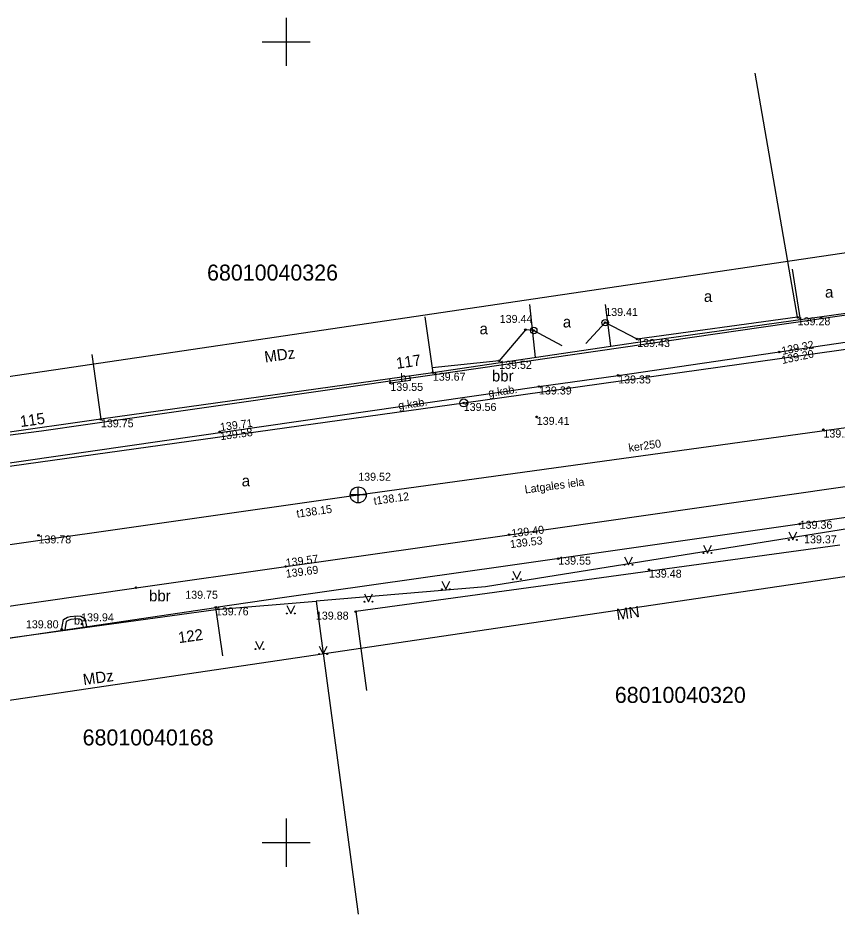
# Model space of a CAD drawing. Extents: x 728785 to 728985, y 273137 to 273208.
# Drawn here: x 728883.2 to 728934.4, y 273145.5 to 273201.5 of the extents above; entities that cross this region are included whole.
import ezdxf

# ---------------------------------------------------------------- set-up
doc = ezdxf.new("R2010")
doc.units = 0
for name, color, linetype in [('APGR_SARK_####_####_#', 7, 'Continuous'), ('BUVE_BDET_####_####_#', 7, 'Continuous'), ('BUVE_BDET_####_TKST_#', 7, 'Continuous'), ('BUVE_EKAS_####_####_#', 7, 'Continuous'), ('BUVE_EKAS_ADRS_TKST_#', 7, 'Continuous'), ('BUVE_EKAS_RAKS_TKST_#', 7, 'Continuous'), ('CELI_CAPM_####_####_#', 7, 'Continuous'), ('CELI_CMAL_####_####_#', 7, 'Continuous'), ('CELI_CSEG_####_TKST_#', 7, 'Continuous'), ('CELI_IELA_####_TKST_#', 7, 'Continuous'), ('ELEK_ELEM_####_####_#', 7, 'Continuous'), ('ELEK_VADV_ZSPR_####_#', 7, 'Continuous'), ('ELEK_VADV_ZSPR_TKST_#', 7, 'Continuous'), ('GEOD_ELEM_####_####_#', 7, 'Continuous'), ('NORB_ELEM_####_####_#', 7, 'Continuous'), ('NORB_ZOGS_ZSTP_####_#', 7, 'Continuous'), ('RELJ_AATZ_####_TKST_#', 7, 'Continuous'), ('RELJ_ELEM_####_####_#', 7, 'Continuous'), ('ROBZ_KADS_####_TKST_#', 7, 'Continuous'), ('ROBZ_UZMR_####_####_#', 7, 'Continuous'), ('SKAN_ELEM_####_####_#', 7, 'Continuous'), ('SKAN_ELEM_PAST_TKST_#', 7, 'Continuous'), ('SKAN_VADP_PAST_####_#', 7, 'Continuous'), ('SKAN_VADP_PAST_TKST_#', 7, 'Continuous'), ('TERT_ELEM_####_####_#', 7, 'Continuous')]:
    doc.layers.add(name, color=color, linetype=linetype)

msp = doc.modelspace()

# ---------------------------------------------------------------- linework, layer by layer
at = {"layer": 'APGR_SARK_####_####_#'}
for points in [[(728955.084, 273187.77), (728943.86, 273188.14), (728816.642, 273169.324)], [(728957.827, 273167.668), (728945.002, 273168.092), (728819.408, 273149.515)]]:
    msp.add_lwpolyline(points, dxfattribs=at)
at = {"layer": 'BUVE_BDET_####_####_#'}
for p, q in [((728907.767, 273178.889), (728907.73, 273179.145)), ((728906.509, 273178.709), (728906.468, 273178.968)), ((728906.509, 273178.709), (728907.767, 273178.889))]:
    msp.add_line(p, q, dxfattribs=at)
for points in [[(728885.974, 273163.262), (728886.081, 273163.935), (728886.346, 273164.087), (728886.515, 273164.125), (728886.941, 273164.169), (728887.184, 273164.149), (728887.422, 273163.993), (728887.535, 273163.494)], [(728887.335, 273163.464), (728887.243, 273163.868), (728887.115, 273163.952), (728886.943, 273163.966), (728886.548, 273163.925), (728886.42, 273163.896), (728886.265, 273163.808), (728886.184, 273163.294)]]:
    msp.add_lwpolyline(points, dxfattribs=at)
at = {"layer": 'BUVE_EKAS_####_####_#'}
for p, q in [((728908.671, 273182.834), (728909.161, 273179.346)), ((728887.858, 273180.487), (728888.427, 273176.436)), ((728909.161, 273179.346), (728888.427, 273176.436)), ((728888.427, 273176.436), (728876.392, 273174.747)), ((728934.577, 273168.568), (728904.348, 273164.427)), ((728880.21, 273162.407), (728895.607, 273164.692)), ((728896.046, 273161.663), (728895.607, 273164.692)), ((728904.348, 273164.427), (728905.012, 273159.511))]:
    msp.add_line(p, q, dxfattribs=at)
at = {"layer": 'CELI_CAPM_####_####_#'}
for points in [[(728857.186, 273170.288), (728877.231, 273172.928), (728915.793, 273178.486), (728920.739, 273179.175), (728935.924, 273181.389)], [(728855.438, 273160.854), (728872.218, 273163.259), (728890.623, 273165.918), (728899.975, 273167.245), (728913.935, 273169.231), (728937.385, 273172.585), (728952.292, 273174.776)]]:
    msp.add_lwpolyline(points, dxfattribs=at)
at = {"layer": 'CELI_CMAL_####_####_#'}
for points in [[(728932.125, 273182.65), (728931.621, 273185.804)], [(728915.567, 273180.287), (728915.213, 273183.6)], [(728920.275, 273181.023), (728919.945, 273183.6)], [(728935.865, 273183.174), (728921.973, 273181.228), (728909.161, 273179.346)], [(728952.265, 273173.086), (728937.162, 273170.62), (728913.708, 273167.266), (728899.747, 273165.28), (728895.607, 273164.692)]]:
    msp.add_lwpolyline(points, dxfattribs=at)
at = {"layer": 'ELEK_ELEM_####_####_#'}
msp.add_circle((728911.092, 273177.457), 0.25, dxfattribs=at)
at = {"layer": 'ELEK_VADV_ZSPR_####_#'}
for p, q in [((728911.092, 273177.457), (728948.158, 273182.674)), ((728864.528, 273170.982), (728911.092, 273177.457))]:
    msp.add_line(p, q, dxfattribs=at)
at = {"layer": 'GEOD_ELEM_####_####_#'}
for p, q in [((728900, 273201.5), (728900, 273200)), ((728898.5, 273200), (728900, 273200)), ((728900, 273200), (728900, 273198.5)), ((728900, 273200), (728901.5, 273200)), ((728900, 273151.5), (728900, 273150)), ((728898.5, 273150), (728900, 273150)), ((728900, 273150), (728900, 273148.5)), ((728900, 273150), (728901.5, 273150))]:
    msp.add_line(p, q, dxfattribs=at)
at = {"layer": 'NORB_ELEM_####_####_#'}
for p, q in [((728919.931, 273182.471), (728918.718, 273181.177)), ((728915.467, 273181.981), (728917.23, 273181.048))]:
    msp.add_line(p, q, dxfattribs=at)
for centre in [(728919.931, 273182.471), (728915.467, 273181.981)]:
    msp.add_circle(centre, 0.202, dxfattribs=at)
at = {"layer": 'NORB_ZOGS_ZSTP_####_#'}
for points in [[(728931.95, 273182.807), (728929.304, 273198.056)], [(728931.95, 273182.807), (728921.93, 273181.449), (728919.931, 273182.471)], [(728915.467, 273181.981), (728914.949, 273182.03), (728913.303, 273180.087), (728909.117, 273179.656)]]:
    msp.add_lwpolyline(points, dxfattribs=at)
at = {"layer": 'RELJ_ELEM_####_####_#'}
for centre in [(728919.931, 273182.471), (728931.95, 273182.807), (728914.949, 273182.03), (728915.467, 273181.981), (728921.93, 273181.449), (728913.303, 273180.087), (728930.806, 273180.643), (728909.161, 273179.346), (728920.739, 273179.175), (728906.509, 273178.709), (728915.793, 273178.486), (728911.092, 273177.457), (728888.427, 273176.436), (728915.655, 273176.587), (728895.854, 273175.652), (728933.561, 273175.793), (728904.501, 273171.712), (728932.075, 273169.9), (728884.528, 273169.186), (728913.935, 273169.231), (728899.975, 273167.244), (728916.997, 273167.728), (728922.66, 273167.047), (728890.623, 273165.918), (728895.607, 273164.692), (728904.348, 273164.427), (728885.976, 273163.322), (728887.249, 273163.653)]:
    msp.add_circle(centre, 0.05, dxfattribs=at)
at = {"layer": 'ROBZ_UZMR_####_####_#'}
for p, q in [((728909.118, 273179.219), (728935.806, 273183.076)), ((728887.62, 273176.127), (728909.118, 273179.219)), ((728876.334, 273174.678), (728884.725, 273175.712)), ((728884.725, 273175.712), (728887.62, 273176.127)), ((728956.923, 273173.1), (728912.452, 273165.969)), ((728912.452, 273165.969), (728901.876, 273165.08)), ((728895.601, 273164.553), (728901.876, 273165.08)), ((728901.876, 273165.08), (728904.493, 273145.539)), ((728880.25, 273162.441), (728895.601, 273164.553))]:
    msp.add_line(p, q, dxfattribs=at)
at = {"layer": 'SKAN_ELEM_####_####_#'}
for p, q in [((728904.501, 273171.212), (728904.501, 273172.212)), ((728905.001, 273171.712), (728904.001, 273171.712))]:
    msp.add_line(p, q, dxfattribs=at)
msp.add_circle((728904.501, 273171.712), 0.5, dxfattribs=at)
at = {"layer": 'SKAN_VADP_PAST_####_#'}
msp.add_lwpolyline([(728858.768, 273165.198), (728904.501, 273171.712), (728961.386, 273179.575)], dxfattribs=at)
at = {"layer": 'TERT_ELEM_####_####_#'}
for p, q in [((728931.409, 273169.404), (728931.659, 273168.904)), ((728931.659, 273168.904), (728931.909, 273169.404)), ((728926.077, 273168.586), (728926.327, 273168.086)), ((728926.327, 273168.086), (728926.577, 273168.586)), ((728921.133, 273167.846), (728921.383, 273167.346)), ((728921.383, 273167.346), (728921.633, 273167.846)), ((728914.166, 273166.95), (728914.416, 273166.45)), ((728914.416, 273166.45), (728914.666, 273166.95)), ((728909.729, 273166.326), (728909.979, 273165.826)), ((728909.979, 273165.826), (728910.229, 273166.326)), ((728904.902, 273165.547), (728905.152, 273165.047)), ((728905.152, 273165.047), (728905.402, 273165.547)), ((728900.037, 273164.807), (728900.287, 273164.307)), ((728900.287, 273164.307), (728900.537, 273164.807)), ((728898.09, 273162.586), (728898.34, 273162.086)), ((728898.34, 273162.086), (728898.59, 273162.586)), ((728902.061, 273162.275), (728902.311, 273161.775)), ((728902.311, 273161.775), (728902.561, 273162.275))]:
    msp.add_line(p, q, dxfattribs=at)
for centre, radius in [((728931.409, 273168.904), 0.028), ((728931.909, 273168.904), 0.0263), ((728926.076, 273168.086), 0.028), ((728926.576, 273168.086), 0.0263), ((728921.133, 273167.345), 0.028), ((728921.633, 273167.345), 0.0263), ((728914.166, 273166.449), 0.028), ((728914.666, 273166.449), 0.0263), ((728909.728, 273165.826), 0.028), ((728910.228, 273165.826), 0.0263), ((728904.902, 273165.047), 0.028), ((728905.402, 273165.047), 0.0263), ((728900.036, 273164.307), 0.028), ((728900.536, 273164.307), 0.0263), ((728898.09, 273162.086), 0.028), ((728898.59, 273162.086), 0.0263), ((728902.06, 273161.774), 0.028), ((728902.56, 273161.774), 0.0263)]:
    msp.add_circle(centre, radius, dxfattribs=at)

# ---------------------------------------------------------------- texts
at = {"layer": 'BUVE_BDET_####_TKST_#'}
for p in [(728907.138, 273178.799), (728886.749, 273163.619)]:
    msp.add_text('b', height=0.5, dxfattribs=at).set_placement(p)
at = {"layer": 'BUVE_EKAS_ADRS_TKST_#'}
for s, rotation, p in [('117', 7.9892, (728906.916, 273179.585)), ('115', 7.9888, (728883.422, 273175.946)), ('122', 7.8336, (728893.298, 273162.453))]:
    msp.add_text(s, height=0.7, rotation=rotation, dxfattribs=at).set_placement(p)
at = {"layer": 'BUVE_EKAS_RAKS_TKST_#'}
for s, rotation, p in [('MDz', 7.9888, (728898.691, 273179.98)), ('MN', 7.8008, (728920.676, 273163.899)), ('MDz', 7.9888, (728887.356, 273159.829))]:
    msp.add_text(s, height=0.7, rotation=rotation, dxfattribs=at).set_placement(p)
at = {"layer": 'CELI_CSEG_####_TKST_#'}
for s, p in [('a', (728926.095, 273183.768)), ('a', (728933.662, 273184.031)), ('a', (728917.283, 273182.171)), ('a', (728912.083, 273181.742)), ('bbr', (728912.852, 273178.799)), ('a', (728897.225, 273172.249)), ('bbr', (728891.437, 273165.069))]:
    msp.add_text(s, height=0.7, dxfattribs=at).set_placement(p)
at = {"layer": 'CELI_IELA_####_TKST_#'}
msp.add_text('Latgales iela', height=0.5, rotation=7.6516, dxfattribs=at).set_placement((728914.934, 273171.799))
at = {"layer": 'ELEK_VADV_ZSPR_TKST_#'}
for rotation, p in [(8.0117, (728912.663, 273177.83)), (7.9166, (728907.038, 273177.045))]:
    msp.add_text('g.kab.', height=0.5, rotation=rotation, dxfattribs=at).set_placement(p)
at = {"layer": 'RELJ_AATZ_####_TKST_#'}
for s, p in [('139.44', (728913.339, 273182.453)), ('139.41', (728919.931, 273182.887)), ('139.28', (728931.95, 273182.307)), ('139.43', (728921.93, 273180.949)), ('139.52', (728913.303, 273179.587)), ('139.67', (728909.161, 273178.846)), ('139.35', (728920.739, 273178.675)), ('139.55', (728906.509, 273178.209)), ('139.39', (728915.793, 273177.986)), ('139.56', (728911.092, 273176.957)), ('139.75', (728888.427, 273175.936)), ('139.41', (728915.655, 273176.087)), ('139.24', (728933.561, 273175.293)), ('139.36', (728932.075, 273169.598)), ('139.78', (728884.528, 273168.686)), ('139.37', (728932.351, 273168.689)), ('139.55', (728916.997, 273167.358)), ('139.48', (728922.66, 273166.547)), ('139.75', (728893.694, 273165.23)), ('139.76', (728895.607, 273164.192)), ('139.94', (728887.191, 273163.821)), ('139.88', (728901.857, 273163.927)), ('139.80', (728883.741, 273163.385))]:
    msp.add_text(s, height=0.5, dxfattribs=at).set_placement(p)
for s, rotation, p in [('139.32', 11.8186, (728931.002, 273180.455)), ('139.20', 11.8186, (728931.002, 273179.885)), ('139.71', 7.6596, (728895.905, 273175.7)), ('139.58', 7.6596, (728895.905, 273175.129)), ('139.40', 6.9257, (728914.107, 273169.063)), ('139.53', 6.9257, (728914.012, 273168.387)), ('139.57', 7.6575, (728900.009, 273167.221)), ('139.69', 7.6575, (728900.009, 273166.538))]:
    msp.add_text(s, height=0.5, rotation=rotation, dxfattribs=at).set_placement(p)
at = {"layer": 'ROBZ_KADS_####_TKST_#'}
for s, p in [('68010040326', (728895.058, 273185.097)), ('68010040320', (728920.533, 273158.726)), ('68010040168', (728887.286, 273156.072))]:
    msp.add_text(s, height=1, dxfattribs=at).set_placement(p)
at = {"layer": 'SKAN_ELEM_PAST_TKST_#'}
msp.add_text('139.52', height=0.5, dxfattribs=at).set_placement((728904.501, 273172.598))
at = {"layer": 'SKAN_VADP_PAST_TKST_#'}
for s, rotation, p in [('ker250', 8.258, (728921.425, 273174.399)), ('t138.12', 7.8699, (728905.499, 273171.089)), ('t138.15', 8.1064, (728900.683, 273170.288))]:
    msp.add_text(s, height=0.5, rotation=rotation, dxfattribs=at).set_placement(p)

doc.saveas('drawing.dxf')
